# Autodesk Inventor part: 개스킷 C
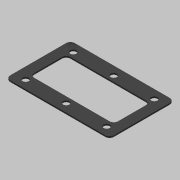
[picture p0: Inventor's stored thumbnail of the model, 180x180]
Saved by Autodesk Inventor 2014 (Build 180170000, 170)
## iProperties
Created: 2020-04
Part Number: 개스킷 C
Material: 고무
Document SubType Name: Modeling
Designer: mduedu
Density: 0.93 g/cm^3
Appearance: Rubber - Black - Version 1.1
Mass: 1.62617 g
Surface Area: 39.8367 cm^2
Volume: 1.74857 cm^3
Author: mduedu
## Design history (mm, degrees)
sketch "스케치1"
  geometry: L1 (37, 23)-(-37, 23); L2 (-37, 23)-(-37, -23); L3 (-37, -23)-(37, -23); L4 (37, -23)-(37, 23); L5 (37, 23)-(-37, -23); L6 (-37, 23)-(37, -23); L7 (30, 13)-(-30, 13); L8 (-30, 13)-(-30, -13); L9 (-30, -13)-(30, -13); L10 (30, -13)-(30, 13); L11 (30, 13)-(-30, -13); L12 (-30, 13)-(30, -13); 1 further point
  constraints: 24 end point, 4 midpoint, 4 parallel, 2 horizontal, 2 perpendicular
  dimensions: "d0" = 74 distance of L3.end L2.end; "d1" = 46 distance of L2.end L1.end; "d2" = 60 distance of L9.end L8.end; "d3" = 26 distance of L8.end L7.end
extrude "돌출1" new body sketch "스케치1" distance "d4" = 1; taper "d5" = 0 deg
fillet "모깎기1" dims "d6" = 3
fillet "모깎기2" dims "d7" = 3
sketch "스케치2"
  geometry: L1 (-29, -17)-(29, -17); L2 (29, -17)-(29, 17); L3 (29, 17)-(-29, 17); L4 (-29, 17)-(-29, -17); L5 (-29, -17)-(29, 17); L6 (29, -17)-(-29, 17); 7 further points
  constraints: 12 end point, 4 coincident, 4 midpoint, 2 parallel, 1 horizontal, 1 perpendicular
  dimensions: "d8" = 58 distance of L3.end L2.end; "d9" = 34 distance of L2.end L1.end
hole "구멍1" sketch "스케치2" at (-29, 17), (29, 17), (29, -17), (-29, -17), (0, 17), (0, -17) diameter "d10" = 4.5; stored, may be unused: countersink angle "d14" = 90 deg, drill point angle "d16" = 118 deg; dims "d11" = 6, "d12" = 4, "d13" = 2, "d15" = 8
node "솔리드1"
